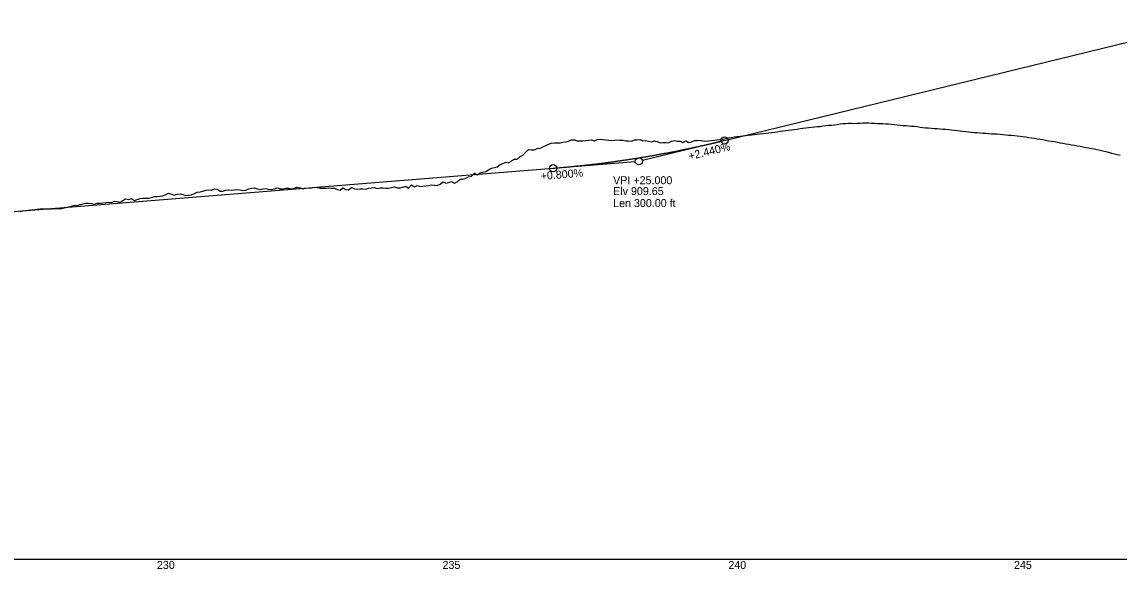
# Model space of a CAD drawing. Extents: x 5180909 to 5237144, y 3695282 to 3720102.
# Drawn here: x 5226506 to 5228426, y 3697765 to 3698722 of the extents above; entities that cross this region are included whole.
import ezdxf

# ---------------------------------------------------------------- set-up
doc = ezdxf.new("R2010")
doc.units = 0
for name, color, linetype in [('dsnEntranceGranular', 7, 'Continuous'), ('dsnShoulderGran', 7, 'Continuous'), ('dsnShoulderPaved', 7, 'Continuous'), ('dsnStgShadingPropGrdLim', 7, 'Continuous'), ('EdgeShoulder', 7, 'Continuous'), ('Entrance', 7, 'Continuous')]:
    doc.layers.add(name, color=color, linetype=linetype)

msp = doc.modelspace()

# ---------------------------------------------------------------- linework, layer by layer
at = {"layer": 'dsnEntranceGranular'}
msp.add_line((5221643.6, 3697782), (5237143.6, 3697782), dxfattribs=at)
at = {"layer": 'dsnShoulderPaved'}
for points in [[(5227642.7, 3698513.6), (5227647.7, 3698515), (5227652.7, 3698513.9), (5227657.7, 3698513.6), (5227662.7, 3698511.7), (5227667.7, 3698514.1), (5227672.7, 3698511.7), (5227677.7, 3698512.5), (5227682.7, 3698514.7), (5227687.7, 3698515.2), (5227692.7, 3698515.6), (5227697.7, 3698514.3), (5227702.7, 3698513.7), (5227707.7, 3698514.2), (5227712.7, 3698514.7), (5227717.7, 3698515.3), (5227722.7, 3698515.8), (5227727.7, 3698516.4), (5227732.7, 3698517.5), (5227737.7, 3698518.5), (5227742.7, 3698519.6), (5227747.7, 3698520.4), (5227752.7, 3698521.1), (5227757.7, 3698521.9), (5227762.7, 3698522.5), (5227767.7, 3698522.9), (5227772.7, 3698523.5), (5227777.7, 3698524.2), (5227782.7, 3698524.8), (5227787.7, 3698525.5), (5227792.7, 3698526.1), (5227797.7, 3698526.8), (5227802.7, 3698527.3), (5227807.7, 3698527.7), (5227812.7, 3698528.1), (5227817.7, 3698528.7), (5227822.7, 3698529.5), (5227827.7, 3698530.2), (5227832.7, 3698531), (5227837.7, 3698531.7), (5227842.7, 3698532.4), (5227847.7, 3698533.1), (5227852.7, 3698533.7), (5227857.7, 3698534.3), (5227862.7, 3698535), (5227867.7, 3698535.8), (5227872.7, 3698536.4), (5227877.7, 3698536.9), (5227882.7, 3698537.5), (5227887.7, 3698538.1), (5227892.7, 3698538.6), (5227897.7, 3698539.2), (5227902.7, 3698539.7), (5227907.7, 3698540.4), (5227912.7, 3698541), (5227917.7, 3698541.5), (5227922.7, 3698542), (5227927.7, 3698542.5), (5227932.7, 3698543.1), (5227937.7, 3698543.8), (5227942.7, 3698544.4), (5227947.7, 3698544.7), (5227952.7, 3698545), (5227957.7, 3698545), (5227962.7, 3698544.9), (5227967.7, 3698545.1), (5227972.7, 3698545.5), (5227977.7, 3698545.7), (5227982.7, 3698545.8), (5227987.7, 3698545.8), (5227992.7, 3698545.4), (5227997.7, 3698545), (5228002.7, 3698544.7), (5228007.7, 3698544.6), (5228012.7, 3698544.4), (5228017.7, 3698544.2), (5228022.7, 3698543.8), (5228027.7, 3698543.4), (5228032.7, 3698542.9), (5228037.7, 3698542.4), (5228042.7, 3698541.9), (5228047.7, 3698541.4), (5228052.7, 3698540.9), (5228057.7, 3698540.5), (5228062.7, 3698540.2), (5228067.7, 3698539.9), (5228072.7, 3698539.2), (5228077.7, 3698538.5), (5228082.7, 3698537.9), (5228087.7, 3698537.3), (5228092.7, 3698536.9), (5228097.7, 3698536.5), (5228102.7, 3698536.1), (5228107.7, 3698535.7), (5228112.7, 3698535.2), (5228117.7, 3698534.7), (5228122.7, 3698534.6), (5228127.7, 3698534.2), (5228132.7, 3698533.7), (5228137.7, 3698533), (5228142.7, 3698532.3)], [(5228142.7, 3698532.3), (5228147.7, 3698531.8), (5228152.7, 3698531.3), (5228157.7, 3698530.8), (5228162.7, 3698530.3), (5228167.7, 3698529.5), (5228172.7, 3698529), (5228177.7, 3698528.8), (5228182.7, 3698528.4), (5228187.7, 3698528), (5228192.7, 3698527.6), (5228197.7, 3698527.2), (5228202.7, 3698526.8), (5228207.7, 3698526.5), (5228212.7, 3698526.3), (5228217.7, 3698526), (5228222.7, 3698525.5), (5228227.7, 3698525.1), (5228232.7, 3698524.5), (5228237.7, 3698524), (5228242.7, 3698523.4), (5228247.7, 3698523.2), (5228252.7, 3698522.7), (5228257.7, 3698522), (5228262.7, 3698521.2), (5228267.7, 3698520.4), (5228272.7, 3698519.6), (5228277.7, 3698518.9), (5228282.7, 3698518.1), (5228287.7, 3698517.3), (5228292.7, 3698516.4), (5228297.7, 3698515.4), (5228302.7, 3698514.5), (5228307.7, 3698513.7), (5228312.7, 3698512.9), (5228317.7, 3698512.1), (5228322.7, 3698511.1), (5228327.7, 3698510.1), (5228332.7, 3698509.2), (5228337.7, 3698508.4), (5228342.7, 3698507.6), (5228347.7, 3698506.8), (5228352.7, 3698505.8), (5228357.7, 3698504.9), (5228362.7, 3698503.9), (5228367.7, 3698502.9), (5228372.7, 3698502), (5228377.7, 3698501), (5228382.7, 3698500.1), (5228387.7, 3698499), (5228392.7, 3698497.9), (5228397.7, 3698496.7), (5228402.7, 3698495.5), (5228407.7, 3698494.3), (5228412.7, 3698493), (5228417.7, 3698491.7), (5228422.7, 3698490.4), (5228427.7, 3698489.2)], [(5227142.7, 3698431.6), (5227147.7, 3698431.5), (5227152.7, 3698432.5), (5227157.7, 3698433.7), (5227162.7, 3698432.3), (5227167.7, 3698431.9), (5227172.7, 3698433), (5227177.7, 3698434.7), (5227182.7, 3698431.3), (5227187.7, 3698437.2), (5227192.7, 3698434.1), (5227197.7, 3698436), (5227202.7, 3698434.2), (5227207.7, 3698435), (5227212.7, 3698435.3), (5227217.7, 3698436.2), (5227222.7, 3698437.4), (5227227.7, 3698436.8), (5227232.7, 3698436.2), (5227237.7, 3698438.5), (5227242.7, 3698442.5), (5227247.7, 3698440.2), (5227252.7, 3698441.6), (5227257.7, 3698443.1), (5227262.7, 3698440), (5227267.7, 3698442.6), (5227272.7, 3698447), (5227277.7, 3698447.1), (5227282.7, 3698448.9), (5227287.7, 3698451.1), (5227292.7, 3698452.2), (5227297.7, 3698457.6), (5227302.7, 3698455.1), (5227307.7, 3698458.1), (5227312.7, 3698459.5), (5227317.7, 3698460.7), (5227322.7, 3698463.6), (5227327.7, 3698466.3), (5227332.7, 3698467.6), (5227337.7, 3698468.9), (5227342.7, 3698473.1), (5227347.7, 3698474.7), (5227352.7, 3698477), (5227357.7, 3698476), (5227362.7, 3698479.5), (5227367.7, 3698482), (5227372.7, 3698482.4), (5227377.7, 3698487), (5227382.7, 3698489.3), (5227387.7, 3698494.7), (5227392.7, 3698499.2), (5227397.7, 3698498.4), (5227402.7, 3698498.6), (5227407.7, 3698500.7), (5227412.7, 3698501.2), (5227417.7, 3698503.7), (5227422.7, 3698506.1), (5227427.7, 3698508.5), (5227432.7, 3698510.5), (5227437.7, 3698511.1), (5227442.7, 3698510.7), (5227447.7, 3698510.7), (5227452.7, 3698512.1), (5227457.7, 3698512.3), (5227462.7, 3698514), (5227467.7, 3698515.8), (5227472.7, 3698516), (5227477.7, 3698514.4), (5227482.7, 3698514.3), (5227487.7, 3698514.2), (5227492.7, 3698514.9), (5227497.7, 3698515.4), (5227502.7, 3698515.9), (5227507.7, 3698514.6), (5227512.7, 3698516.4), (5227517.7, 3698517.2), (5227522.7, 3698516.6), (5227527.7, 3698515.9), (5227532.7, 3698515.3), (5227537.7, 3698515.2), (5227542.7, 3698515.4), (5227547.7, 3698515.9), (5227552.7, 3698515.3), (5227557.7, 3698515.6), (5227562.7, 3698514.4), (5227567.7, 3698514.6), (5227572.7, 3698513.5), (5227577.7, 3698516.1), (5227582.7, 3698516.2), (5227587.7, 3698516.4), (5227592.7, 3698514.3), (5227597.7, 3698514.7), (5227602.7, 3698514), (5227607.7, 3698512.5), (5227612.7, 3698514.3), (5227617.7, 3698513.2), (5227622.7, 3698510.9), (5227627.7, 3698511.2), (5227632.7, 3698511.2), (5227637.7, 3698510.9), (5227642.7, 3698513.6)], [(5226642.7, 3698405.4), (5226647.7, 3698405.7), (5226652.7, 3698406.3), (5226657.7, 3698406.8), (5226662.7, 3698406.4), (5226667.7, 3698408.9), (5226672.7, 3698408.2), (5226677.7, 3698407.1), (5226682.7, 3698409.9), (5226687.7, 3698412.6), (5226692.7, 3698411.6), (5226697.7, 3698413.2), (5226702.7, 3698410.1), (5226707.7, 3698411.4), (5226712.7, 3698413.6), (5226717.7, 3698413.7), (5226722.7, 3698413.8), (5226727.7, 3698413.8), (5226732.7, 3698415.4), (5226737.7, 3698416.6), (5226742.7, 3698416.6), (5226747.7, 3698417.4), (5226752.7, 3698418.1), (5226757.7, 3698420.3), (5226762.7, 3698422.5), (5226767.7, 3698421.2), (5226772.7, 3698419.3), (5226777.7, 3698421), (5226782.7, 3698421.3), (5226787.7, 3698420.1), (5226792.7, 3698418.8), (5226797.7, 3698419.2), (5226802.7, 3698419.7), (5226807.7, 3698422.3), (5226812.7, 3698424.2), (5226817.7, 3698425.3), (5226822.7, 3698426.4), (5226827.7, 3698427.8), (5226832.7, 3698428.4), (5226837.7, 3698428.2), (5226842.7, 3698430.5), (5226847.7, 3698429.7), (5226852.7, 3698426.5), (5226857.7, 3698426.3), (5226862.7, 3698428.2), (5226867.7, 3698428.6), (5226872.7, 3698428), (5226877.7, 3698428.4), (5226882.7, 3698428.9), (5226887.7, 3698428.7), (5226892.7, 3698427.6), (5226897.7, 3698427.7), (5226902.7, 3698430.5), (5226907.7, 3698431.2), (5226912.7, 3698431.9), (5226917.7, 3698430.6), (5226922.7, 3698429), (5226927.7, 3698430.3), (5226932.7, 3698430.8), (5226937.7, 3698429.8), (5226942.7, 3698429.4), (5226947.7, 3698430.6), (5226952.7, 3698432.1), (5226957.7, 3698430.4), (5226962.7, 3698430.6), (5226967.7, 3698431.6), (5226972.7, 3698431.5), (5226977.7, 3698430.1), (5226982.7, 3698431.5), (5226987.7, 3698433.1), (5226992.7, 3698431.8), (5226997.7, 3698430.5), (5227002.7, 3698431.6), (5227007.7, 3698431.9), (5227012.7, 3698431.9), (5227017.7, 3698433.1), (5227022.7, 3698432.8), (5227027.7, 3698431.2), (5227032.7, 3698431.3), (5227037.7, 3698431.6), (5227042.7, 3698432.1), (5227047.7, 3698431.4), (5227052.7, 3698431.6), (5227057.7, 3698429.3), (5227062.7, 3698427.8), (5227067.7, 3698431.9), (5227072.7, 3698429.3), (5227077.7, 3698428.7), (5227082.7, 3698432.7), (5227087.7, 3698430.1), (5227092.7, 3698429.8), (5227097.7, 3698430.6), (5227102.7, 3698430.3), (5227107.7, 3698429.6), (5227112.7, 3698431.4), (5227117.7, 3698432), (5227122.7, 3698432.9), (5227127.7, 3698431.1), (5227132.7, 3698431.8), (5227137.7, 3698431.8), (5227142.7, 3698431.6)], [(5226502.7, 3698390.8), (5226507.7, 3698391.6), (5226512.7, 3698392.1), (5226517.7, 3698392.8), (5226522.7, 3698393.5), (5226527.7, 3698394.3), (5226532.7, 3698395), (5226537.7, 3698395.4), (5226542.7, 3698395.5), (5226547.7, 3698395.1), (5226552.7, 3698395.1), (5226557.7, 3698395.2), (5226562.7, 3698395.6), (5226567.7, 3698395.7), (5226572.7, 3698395.5), (5226577.7, 3698396.4), (5226582.7, 3698397.6), (5226587.7, 3698398.7), (5226592.7, 3698400.1), (5226597.7, 3698401.6), (5226602.7, 3698401.4), (5226607.7, 3698402.7), (5226612.7, 3698404.3), (5226617.7, 3698405), (5226622.7, 3698405.4), (5226627.7, 3698404.9), (5226632.7, 3698403.2), (5226637.7, 3698405.3), (5226642.7, 3698405.4)]]:
    msp.add_lwpolyline(points, dxfattribs=at)
at = {"layer": 'dsnStgShadingPropGrdLim'}
for p, q in [((5227735.6, 3698515), (5228585.6, 3698722.4)), ((5226460.6, 3698388.4), (5227435.6, 3698466.4))]:
    msp.add_line(p, q, dxfattribs=at)
msp.add_spline([(5227435.6, 3698466.4), (5227441.6, 3698466.9), (5227447.6, 3698467.4), (5227453.6, 3698468), (5227459.6, 3698468.5), (5227465.6, 3698469.1), (5227471.6, 3698469.7), (5227477.6, 3698470.3), (5227483.6, 3698470.9), (5227489.6, 3698471.6), (5227495.6, 3698472.2), (5227501.6, 3698472.9), (5227507.6, 3698473.6), (5227513.6, 3698474.3), (5227519.6, 3698475.1), (5227525.6, 3698475.9), (5227531.6, 3698476.6), (5227537.6, 3698477.4), (5227543.6, 3698478.3), (5227549.6, 3698479.1), (5227555.6, 3698480), (5227561.6, 3698480.9), (5227567.6, 3698481.8), (5227573.6, 3698482.7), (5227579.6, 3698483.6), (5227585.6, 3698484.6), (5227591.6, 3698485.6), (5227597.6, 3698486.6), (5227603.6, 3698487.6), (5227609.6, 3698488.6), (5227615.6, 3698489.7), (5227621.6, 3698490.8), (5227627.6, 3698491.9), (5227633.6, 3698493), (5227639.6, 3698494.1), (5227645.6, 3698495.3), (5227651.6, 3698496.5), (5227657.6, 3698497.7), (5227663.6, 3698498.9), (5227669.6, 3698500.1), (5227675.6, 3698501.4), (5227681.6, 3698502.7), (5227687.6, 3698504), (5227693.6, 3698505.3), (5227699.6, 3698506.6), (5227705.6, 3698508), (5227711.6, 3698509.3), (5227717.6, 3698510.7), (5227723.6, 3698512.1), (5227729.6, 3698513.6), (5227735.6, 3698515)], degree=3, dxfattribs=at)
at = {"layer": 'Entrance'}
for p, q in [((5227735.6, 3698515), (5227591.7, 3698479.9)), ((5227435.6, 3698466.4), (5227579.4, 3698477.9))]:
    msp.add_line(p, q, dxfattribs=at)
for centre in [(5227735.6, 3698515), (5227435.6, 3698466.4), (5227585.6, 3698478.4)]:
    msp.add_circle(centre, 6.25, dxfattribs=at)

# ---------------------------------------------------------------- texts
at = {"layer": 'dsnShoulderGran'}
for s, p in [('230', (5226742.2, 3697765)), ('235', (5227242, 3697765)), ('240', (5227742.2, 3697765)), ('245', (5228242, 3697765))]:
    msp.add_text(s, height=14, dxfattribs=at).set_placement(p)
at = {"layer": 'EdgeShoulder'}
for s, rotation, p in [('+2.440%', 13.7122, (5227674.3, 3698480.5)), ('+0.800%', 4.5739, (5227414.3, 3698445.7))]:
    msp.add_text(s, height=14, rotation=rotation, dxfattribs=at).set_placement(p)
for s, p in [('VPI +25.000', (5227540.6, 3698438.4)), ('Elv 909.65', (5227540.6, 3698419.4)), ('Len 300.00 ft', (5227540.6, 3698398.4))]:
    msp.add_text(s, height=14, dxfattribs=at).set_placement(p)

doc.saveas('drawing.dxf')
